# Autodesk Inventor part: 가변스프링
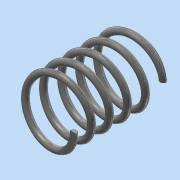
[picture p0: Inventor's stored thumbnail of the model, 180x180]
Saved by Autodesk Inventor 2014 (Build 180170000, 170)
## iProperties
Created: 2024-02
Part Number: 가변스프링
Material: 스테인레스 스틸
Document SubType Name: Modeling
Designer: dg
Density: 8.08 g/cm^3
Appearance: 반연마
Mass: 7.07035 g
Surface Area: 17.7554 cm^2
Volume: 0.875043 cm^3
Author: dg
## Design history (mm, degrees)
sketch "스케치1"
  geometry: L1 (9, 0)-(0, 0); L2 (0, 0)-(0, 28.5); L3 (0, 28.5)-(9, 28.5); C1 r 1 at (9, 0)
  constraints: 6 end point, 2 parallel, 1 centre point, 1 coincident, 1 horizontal, 1 perpendicular
  dimensions: "d0" = 2 diameter of C1; "d1" = 18 diameter of L1.start L2; "d2" = 28.5 distance of L1.end L2.end (derived)
feature "코일1" sketch "스케치1" pitch "d3" = 10; turns "d5" = 5; dims "d4" = 28.49994 (computed from d2), "d6" = 0, angle "d7" = 90 deg, angle "d8" = 90 deg, "d9" = 0, "d10" = 0
node "작업 평면1"
feature "분할1"
feature "분할2"
node "솔리드1"
other parameters: "d11" = 0
